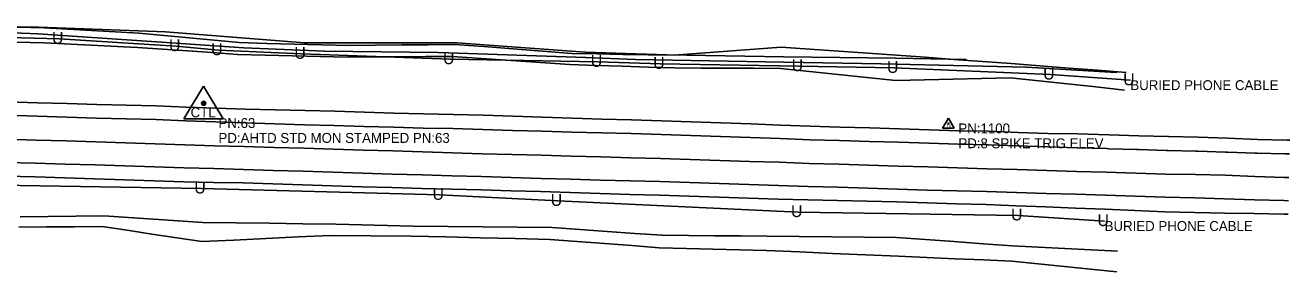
# Model space of a CAD drawing. Extents: x 976456 to 985170, y 1525951 to 1527080.
# Drawn here: x 983350 to 983988, y 1526256 to 1526381 of the extents above; entities that cross this region are included whole.
import ezdxf

# ---------------------------------------------------------------- set-up
doc = ezdxf.new("R2010")
doc.units = 0
for name, color, linetype in [('Default', 7, 'Continuous'), ('S_DITCHLINE', 7, 'Continuous'), ('S_EDGE_PAVEMENT', 7, 'Continuous'), ('S_FIBER_OPTIC_CABLE', 7, 'Continuous'), ('S_PAVEMENT_CROWN', 7, 'Continuous'), ('S_PRIMARY_CTL', 7, 'Continuous'), ('S_PRIMARY_CTL_ANNOT', 7, 'Continuous'), ('S_SECONDARY_CTL', 7, 'Continuous'), ('S_SECONDARY_CTL_ANNOT', 7, 'Continuous'), ('S_SHOULDER', 7, 'Continuous'), ('S_UNDERGROUND_CABLE', 7, 'Continuous'), ('S_UNDERGROUND_CABLE_ANNOT', 7, 'Continuous'), ('S_UTL_PT_SYM', 7, 'Continuous')]:
    doc.layers.add(name, color=color, linetype=linetype)

msp = doc.modelspace()

# ---------------------------------------------------------------- linework, layer by layer
at = {"layer": 'S_DITCHLINE'}
for points in [[(983905.63, 1526356.89), (983891.1, 1526358.02), (983876.57, 1526359.16), (983862.04, 1526360.29), (983847.51, 1526361.42), (983833.07, 1526362.47), (983818.62, 1526363.52), (983804.18, 1526364.56), (983789.74, 1526365.61), (983775.18, 1526366.63), (983760.61, 1526367.65), (983746.05, 1526368.67), (983731.48, 1526369.68), (983718, 1526368.66), (983704.52, 1526367.64), (983691.04, 1526366.62), (983677.56, 1526365.59), (983664.64, 1526365.83), (983651.73, 1526366.07), (983638.81, 1526366.31), (983625.89, 1526366.55), (983611.09, 1526367.68), (983596.29, 1526368.82), (983581.49, 1526369.96), (983566.69, 1526371.09), (983553.41, 1526370.95), (983540.12, 1526370.81), (983526.83, 1526370.67), (983513.54, 1526370.53), (983499.71, 1526370.89), (983485.87, 1526371.25), (983472.03, 1526371.61), (983458.19, 1526371.97), (983445.54, 1526373.18), (983432.9, 1526374.39), (983420.25, 1526375.6), (983407.6, 1526376.81), (983383.71, 1526378.12), (983359.82, 1526379.42), (983346.11, 1526379.83)], [(983904.73, 1526348.04), (983890.32, 1526349.6), (983875.92, 1526351.16), (983861.51, 1526352.72), (983847.1, 1526354.28), (983832.66, 1526353.91), (983818.23, 1526353.54), (983803.79, 1526353.17), (983789.36, 1526352.8), (983774.82, 1526354.33), (983760.28, 1526355.87), (983745.75, 1526357.41), (983731.21, 1526358.94), (983717.82, 1526359.01), (983704.43, 1526359.08), (983691.04, 1526359.15), (983677.65, 1526359.22), (983664.49, 1526359.64), (983651.32, 1526360.05), (983638.16, 1526360.47), (983625, 1526360.88), (983610.13, 1526361.9), (983595.26, 1526362.92), (983580.39, 1526363.94), (983565.53, 1526364.96), (983552.34, 1526364.9), (983539.16, 1526364.84), (983525.98, 1526364.78), (983512.8, 1526364.72), (983498.93, 1526365.05), (983485.07, 1526365.38), (983471.2, 1526365.72), (983457.33, 1526366.05), (983444.71, 1526366.94), (983432.1, 1526367.83), (983419.48, 1526368.72), (983406.86, 1526369.6), (983383.3, 1526370.76), (983359.74, 1526371.92), (983345.64, 1526372.19)], [(983901.19, 1526266.61), (983887.89, 1526267.32), (983874.59, 1526268.03), (983861.29, 1526268.74), (983847.99, 1526269.45), (983833.43, 1526270.47), (983818.88, 1526271.49), (983804.33, 1526272.52), (983789.77, 1526273.54), (983773.4, 1526273.74), (983757.03, 1526273.94), (983740.65, 1526274.14), (983724.28, 1526274.33), (983711.09, 1526274.42), (983697.9, 1526274.51), (983684.71, 1526274.6), (983671.52, 1526274.69), (983657.66, 1526275.68), (983643.79, 1526276.67), (983629.93, 1526277.66), (983616.06, 1526278.65), (983598.54, 1526278.82), (983581.02, 1526279.01), (983563.5, 1526279.19), (983545.98, 1526279.36), (983526.46, 1526279.86), (983506.93, 1526280.36), (983490.17, 1526280.56), (983473.41, 1526280.77), (983456.64, 1526280.98), (983439.88, 1526281.19), (983427.38, 1526282.01), (983414.88, 1526282.84), (983402.37, 1526283.66), (983389.87, 1526284.49), (983375.81, 1526284.32), (983361.76, 1526284.16), (983347.7, 1526284)], [(983900.88, 1526256.3), (983887.64, 1526257.65), (983874.39, 1526258.99), (983861.15, 1526260.33), (983847.91, 1526261.67), (983833.6, 1526262.28), (983819.3, 1526262.89), (983805, 1526263.51), (983790.7, 1526264.12), (983774.04, 1526264.84), (983757.37, 1526265.57), (983740.71, 1526266.29), (983724.05, 1526267.02), (983710.55, 1526267.36), (983697.05, 1526267.71), (983683.54, 1526268.05), (983670.04, 1526268.4), (983656.23, 1526269.47), (983642.42, 1526270.53), (983628.61, 1526271.59), (983614.8, 1526272.66), (983597.33, 1526273.08), (983579.86, 1526273.49), (983562.4, 1526273.91), (983544.93, 1526274.32), (983524.55, 1526274.49), (983504.18, 1526274.65), (983487.95, 1526273.86), (983471.73, 1526273.08), (983455.5, 1526272.3), (983439.27, 1526271.52), (983426.7, 1526273.42), (983414.13, 1526275.33), (983401.56, 1526277.24), (983388.99, 1526279.15), (983374.98, 1526279.06), (983360.97, 1526278.97), (983346.96, 1526278.88)]]:
    msp.add_lwpolyline(points, dxfattribs=at)
at = {"layer": 'S_EDGE_PAVEMENT'}
for points in [[(983341.18, 1526335.31), (983356.17, 1526334.78), (983371.16, 1526334.35), (983386.15, 1526333.89), (983401.15, 1526333.56), (983416.14, 1526333.1), (983431.12, 1526332.49), (983446.15, 1526332.01), (983461.14, 1526331.51), (983476.13, 1526331.01), (983491.12, 1526330.52), (983506.12, 1526330.16), (983521.11, 1526329.7), (983536, 1526329.22), (983550.99, 1526328.83), (983565.99, 1526328.57), (983580.98, 1526328.08), (983595.97, 1526327.69), (983610.96, 1526327.23), (983625.96, 1526326.83), (983640.95, 1526326.44), (983655.94, 1526326.04), (983670.93, 1526325.57), (983685.92, 1526325.02), (983700.91, 1526324.54), (983716, 1526324.05), (983730.99, 1526323.53), (983745.98, 1526322.95), (983745.98, 1526322.95), (983760.97, 1526322.5), (983775.96, 1526322.04), (983790.95, 1526321.68), (983805.94, 1526321.2), (983820.88, 1526320.72), (983835.88, 1526320.39), (983850.87, 1526319.92), (983865.86, 1526319.45), (983880.85, 1526318.91), (983895.84, 1526318.45), (983896.83, 1526318.42), (983910.83, 1526318.03), (983911.82, 1526318), (983925.7, 1526317.58), (983926.69, 1526317.55), (983940.69, 1526317.24), (983941.69, 1526317.22), (983955.68, 1526316.73), (983956.68, 1526316.7), (983970.68, 1526316.17), (983971.67, 1526316.13), (983985.67, 1526315.81), (983986.66, 1526315.79), (983987.92, 1526315.77)], [(983340.46, 1526311.52), (983355.45, 1526311.16), (983370.44, 1526310.66), (983385.44, 1526310.21), (983400.43, 1526309.74), (983415.42, 1526309.28), (983430.41, 1526308.85), (983445.37, 1526308.38), (983460.36, 1526307.91), (983475.35, 1526307.45), (983475.35, 1526307.45), (983490.35, 1526307), (983505.34, 1526306.51), (983520.33, 1526305.99), (983520.33, 1526305.99), (983535.39, 1526305.6), (983550.38, 1526305.21), (983565.38, 1526304.78), (983580.37, 1526304.32), (983580.37, 1526304.32), (983595.36, 1526303.92), (983610.35, 1526303.46), (983625.34, 1526303.08), (983640.33, 1526302.61), (983655.33, 1526302.19), (983655.33, 1526302.19), (983670.32, 1526301.79), (983685.31, 1526301.39), (983700.3, 1526300.89), (983715.22, 1526300.41), (983715.22, 1526300.41), (983730.2, 1526299.77), (983745.19, 1526299.26), (983760.19, 1526298.95), (983775.18, 1526298.47), (983790.17, 1526297.95), (983805.16, 1526297.45), (983820.2, 1526297.08), (983835.19, 1526296.74), (983850.18, 1526296.29), (983865.17, 1526295.86), (983880.17, 1526295.4), (983895.16, 1526294.89), (983910.15, 1526294.46), (983925.23, 1526293.98), (983940.23, 1526293.56), (983955.22, 1526293.14), (983955.22, 1526293.14), (983970.21, 1526292.66), (983970.21, 1526292.66), (983985.21, 1526292.21), (983985.21, 1526292.21), (983987.45, 1526292.17)]]:
    msp.add_lwpolyline(points, dxfattribs=at)
at = {"layer": 'S_FIBER_OPTIC_CABLE'}
for p, q in [((983357.07, 1526379.84), (983275.76, 1526380.75)), ((983420.95, 1526377.36), (983357.07, 1526379.84)), ((983356.57, 1526376.42), (983309.05, 1526378.18)), ((983419.01, 1526372.27), (983356.57, 1526376.42)), ((983491.02, 1526371.87), (983420.95, 1526377.36)), ((983460.54, 1526369.3), (983419.01, 1526372.27)), ((983501.17, 1526367.66), (983460.54, 1526369.3)), ((983491.14, 1526371.89), (983491.02, 1526371.87)), ((983567.99, 1526371.81), (983491.14, 1526371.89)), ((983558.49, 1526366.98), (983501.17, 1526367.66)), ((983632.95, 1526364.42), (983558.49, 1526366.98)), ((983632.74, 1526367.18), (983567.99, 1526371.81)), ((983673.79, 1526365.84), (983632.74, 1526367.18)), ((983658, 1526363.4), (983632.95, 1526364.42)), ((983732.98, 1526362.1), (983658, 1526363.4)), ((983732.84, 1526364.86), (983673.79, 1526365.84)), ((983789.3, 1526364.14), (983732.84, 1526364.86)), ((983781.94, 1526361.21), (983732.98, 1526362.1)), ((983855.1, 1526359.6), (983781.94, 1526361.21)), ((983824.69, 1526363.46), (983789.3, 1526364.14)), ((983900.54, 1526356.92), (983855.1, 1526359.6))]:
    msp.add_line(p, q, dxfattribs=at)
at = {"layer": 'S_PAVEMENT_CROWN'}
msp.add_lwpolyline([(983340.81, 1526323.18), (983355.8, 1526322.78), (983370.79, 1526322.38), (983385.79, 1526321.93), (983400.78, 1526321.47), (983415.77, 1526320.89), (983430.76, 1526320.42), (983445.75, 1526319.93), (983460.74, 1526319.46), (983475.74, 1526319.09), (983490.73, 1526318.67), (983505.72, 1526318.2), (983520.71, 1526317.77), (983535.69, 1526317.28), (983550.68, 1526316.89), (983565.67, 1526316.4), (983580.66, 1526315.84), (983595.66, 1526315.51), (983610.65, 1526315.11), (983625.64, 1526314.73), (983640.63, 1526314.34), (983655.62, 1526313.82), (983670.62, 1526313.43), (983685.61, 1526313.03), (983700.6, 1526312.48), (983715.6, 1526312.03), (983730.59, 1526311.56), (983745.58, 1526311), (983760.57, 1526310.57), (983775.56, 1526310.08), (983790.55, 1526309.58), (983805.55, 1526309.21), (983820.53, 1526308.75), (983835.52, 1526308.31), (983850.52, 1526307.91), (983865.51, 1526307.39), (983880.49, 1526306.96), (983895.48, 1526306.52), (983910.48, 1526306.08), (983925.46, 1526305.65), (983940.45, 1526305.37), (983955.45, 1526305.08), (983970.44, 1526304.45), (983985.43, 1526303.95), (983987.68, 1526303.9)], dxfattribs=at)
at = {"layer": 'S_PRIMARY_CTL'}
for p, q in [((983440.21, 1526350.07), (983430.17, 1526333.56)), ((983440.21, 1526350.07), (983450.03, 1526333.56)), ((983430.17, 1526333.56), (983450.03, 1526333.56))]:
    msp.add_line(p, q, dxfattribs=at)
for radius in [1.04, 0.609, 0.344]:
    msp.add_circle((983440.21, 1526341.37), radius, dxfattribs=at)
at = {"layer": 'S_SECONDARY_CTL'}
for p, q in [((983815.93, 1526333.78), (983812.92, 1526328.82)), ((983812.92, 1526328.82), (983818.88, 1526328.82)), ((983815.93, 1526333.78), (983818.88, 1526328.82))]:
    msp.add_line(p, q, dxfattribs=at)
for radius in [0.311, 0.183, 0.103]:
    msp.add_circle((983815.93, 1526331.17), radius, dxfattribs=at)
at = {"layer": 'S_SHOULDER'}
for points in [[(983341.38, 1526342.17), (983356.37, 1526341.65), (983371.36, 1526341.21), (983386.36, 1526340.77), (983401.35, 1526340.44), (983416.34, 1526340), (983431.33, 1526339.37), (983446.38, 1526338.91), (983461.37, 1526338.41), (983476.37, 1526338.13), (983491.36, 1526337.64), (983506.36, 1526337.38), (983521.35, 1526336.91), (983536.19, 1526336.43), (983551.18, 1526336.04), (983566.18, 1526335.77), (983581.17, 1526335.28), (983596.16, 1526334.89), (983611.15, 1526334.38), (983626.14, 1526333.88), (983641.13, 1526333.42), (983656.12, 1526333.02), (983671.11, 1526332.55), (983686.1, 1526331.93), (983701.09, 1526331.44), (983716.23, 1526330.96), (983731.21, 1526330.37), (983746.2, 1526329.79), (983761.19, 1526329.35), (983776.18, 1526328.89), (983791.18, 1526328.5), (983806.17, 1526328.01), (983821.08, 1526327.53), (983836.07, 1526327.2), (983851.06, 1526326.67), (983866.05, 1526326.09), (983881.05, 1526325.94), (983897.04, 1526325.44), (983912.03, 1526324.99), (983926.83, 1526324.56), (983941.82, 1526324.24), (983956.82, 1526323.77), (983971.81, 1526323.13), (983986.8, 1526322.79), (983988.05, 1526322.77)], [(983340.25, 1526304.51), (983355.24, 1526304.2), (983370.23, 1526303.64), (983385.22, 1526303.19), (983400.21, 1526302.7), (983415.21, 1526302.23), (983430.2, 1526301.74), (983445.14, 1526301.39), (983460.14, 1526301.12), (983475.13, 1526300.63), (983490.12, 1526300.11), (983505.11, 1526299.61), (983520.1, 1526299.2), (983535.22, 1526298.8), (983550.21, 1526298.38), (983565.2, 1526298), (983580.2, 1526297.62), (983595.19, 1526297.2), (983610.18, 1526296.74), (983625.17, 1526296.34), (983640.16, 1526295.88), (983655.15, 1526295.36), (983670.14, 1526294.93), (983685.14, 1526294.52), (983700.13, 1526294.01), (983714.99, 1526293.52), (983729.98, 1526292.94), (983744.98, 1526292.63), (983759.97, 1526292.27), (983774.97, 1526291.9), (983789.96, 1526291.52), (983804.95, 1526291.02), (983820.01, 1526290.65), (983835, 1526290.17), (983849.99, 1526289.6), (983864.98, 1526289.05), (983879.96, 1526288.44), (983894.95, 1526287.89), (983909.94, 1526287.27), (983925.09, 1526286.59), (983940.09, 1526286.21), (983955.08, 1526285.81), (983970.08, 1526285.78), (983985.08, 1526285.34), (983987.32, 1526285.3)]]:
    msp.add_lwpolyline(points, dxfattribs=at)
at = {"layer": 'S_UNDERGROUND_CABLE'}
for p, q in [((983367.37, 1526373.97), (983316.69, 1526375.31)), ((983426.37, 1526370.25), (983367.37, 1526373.97)), ((983447.64, 1526368.2), (983426.37, 1526370.25)), ((983489.59, 1526366.36), (983447.64, 1526368.2)), ((983564.59, 1526363.67), (983489.59, 1526366.36)), ((983639.11, 1526362.33), (983564.59, 1526363.67)), ((983670.62, 1526361.33), (983639.11, 1526362.33)), ((983740.46, 1526360.13), (983670.62, 1526361.33)), ((983788.55, 1526359.23), (983740.46, 1526360.13)), ((983867.31, 1526355.89), (983788.55, 1526359.23)), ((983907.68, 1526353.02), (983867.31, 1526355.89)), ((983439.12, 1526298.37), (983337.28, 1526299.97)), ((983559.3, 1526295.17), (983439.12, 1526298.37)), ((983618.91, 1526292.09), (983559.3, 1526295.17)), ((983740.11, 1526286.44), (983618.91, 1526292.09)), ((983851.11, 1526284.77), (983740.11, 1526286.44)), ((983894.71, 1526281.9), (983851.11, 1526284.77))]:
    msp.add_line(p, q, dxfattribs=at)
at = {"layer": 'S_UTL_PT_SYM'}
for points in [[(983357.07, 1526379.84), (983357.07, 1526379.89), (983357.07, 1526379.84), (983357.02, 1526379.84), (983357.07, 1526379.84), (983357.07, 1526379.79), (983357.07, 1526379.84), (983357.12, 1526379.84)], [(983356.57, 1526376.42), (983356.57, 1526376.47), (983356.57, 1526376.42), (983356.52, 1526376.42), (983356.57, 1526376.42), (983356.57, 1526376.37), (983356.57, 1526376.42), (983356.62, 1526376.42)], [(983420.95, 1526377.36), (983420.95, 1526377.41), (983420.95, 1526377.36), (983420.9, 1526377.36), (983420.95, 1526377.36), (983420.95, 1526377.31), (983420.95, 1526377.36), (983421, 1526377.36)], [(983419.01, 1526372.27), (983419.01, 1526372.32), (983419.01, 1526372.27), (983418.96, 1526372.27), (983419.01, 1526372.27), (983419.01, 1526372.22), (983419.01, 1526372.27), (983419.06, 1526372.27)], [(983460.54, 1526369.3), (983460.54, 1526369.35), (983460.54, 1526369.3), (983460.49, 1526369.3), (983460.54, 1526369.3), (983460.54, 1526369.25), (983460.54, 1526369.3), (983460.59, 1526369.3)], [(983491.02, 1526371.87), (983491.02, 1526371.92), (983491.02, 1526371.87), (983490.97, 1526371.87), (983491.02, 1526371.87), (983491.02, 1526371.82), (983491.02, 1526371.87), (983491.07, 1526371.87)], [(983491.14, 1526371.89), (983491.14, 1526371.94), (983491.14, 1526371.89), (983491.09, 1526371.89), (983491.14, 1526371.89), (983491.14, 1526371.84), (983491.14, 1526371.89), (983491.19, 1526371.89)], [(983501.17, 1526367.66), (983501.17, 1526367.71), (983501.17, 1526367.66), (983501.12, 1526367.66), (983501.17, 1526367.66), (983501.17, 1526367.61), (983501.17, 1526367.66), (983501.22, 1526367.66)], [(983558.49, 1526366.98), (983558.49, 1526367.03), (983558.49, 1526366.98), (983558.44, 1526366.98), (983558.49, 1526366.98), (983558.49, 1526366.93), (983558.49, 1526366.98), (983558.54, 1526366.98)], [(983567.99, 1526371.81), (983567.99, 1526371.86), (983567.99, 1526371.81), (983567.94, 1526371.81), (983567.99, 1526371.81), (983567.99, 1526371.76), (983567.99, 1526371.81), (983568.04, 1526371.81)], [(983632.74, 1526367.18), (983632.74, 1526367.23), (983632.74, 1526367.18), (983632.69, 1526367.18), (983632.74, 1526367.18), (983632.74, 1526367.13), (983632.74, 1526367.18), (983632.79, 1526367.18)], [(983632.95, 1526364.42), (983632.95, 1526364.47), (983632.95, 1526364.42), (983632.9, 1526364.42), (983632.95, 1526364.42), (983632.95, 1526364.37), (983632.95, 1526364.42), (983633, 1526364.42)], [(983658, 1526363.4), (983658, 1526363.45), (983658, 1526363.4), (983657.95, 1526363.4), (983658, 1526363.4), (983658, 1526363.35), (983658, 1526363.4), (983658.05, 1526363.4)], [(983673.79, 1526365.84), (983673.79, 1526365.89), (983673.79, 1526365.84), (983673.74, 1526365.84), (983673.79, 1526365.84), (983673.79, 1526365.79), (983673.79, 1526365.84), (983673.84, 1526365.84)], [(983732.84, 1526364.86), (983732.84, 1526364.91), (983732.84, 1526364.86), (983732.79, 1526364.86), (983732.84, 1526364.86), (983732.84, 1526364.81), (983732.84, 1526364.86), (983732.89, 1526364.86)], [(983732.98, 1526362.1), (983732.98, 1526362.15), (983732.98, 1526362.1), (983732.93, 1526362.1), (983732.98, 1526362.1), (983732.98, 1526362.05), (983732.98, 1526362.1), (983733.03, 1526362.1)], [(983781.94, 1526361.21), (983781.94, 1526361.26), (983781.94, 1526361.21), (983781.89, 1526361.21), (983781.94, 1526361.21), (983781.94, 1526361.16), (983781.94, 1526361.21), (983781.99, 1526361.21)], [(983789.3, 1526364.14), (983789.3, 1526364.19), (983789.3, 1526364.14), (983789.25, 1526364.14), (983789.3, 1526364.14), (983789.3, 1526364.09), (983789.3, 1526364.14), (983789.35, 1526364.14)], [(983824.69, 1526363.46), (983824.69, 1526363.51), (983824.69, 1526363.46), (983824.64, 1526363.46), (983824.69, 1526363.46), (983824.69, 1526363.41), (983824.69, 1526363.46), (983824.74, 1526363.46)], [(983855.1, 1526359.6), (983855.1, 1526359.65), (983855.1, 1526359.6), (983855.05, 1526359.6), (983855.1, 1526359.6), (983855.1, 1526359.55), (983855.1, 1526359.6), (983855.15, 1526359.6)], [(983900.54, 1526356.92), (983900.54, 1526356.97), (983900.54, 1526356.92), (983900.49, 1526356.92), (983900.54, 1526356.92), (983900.54, 1526356.87), (983900.54, 1526356.92), (983900.59, 1526356.92)]]:
    msp.add_lwpolyline(points, dxfattribs=at)

# ---------------------------------------------------------------- texts
at = {"layer": 'Default'}
for p in [(983363.74, 1526371.43), (983422.74, 1526367.71), (983444.01, 1526365.65), (983485.96, 1526363.82), (983560.96, 1526361.12), (983635.48, 1526359.78), (983666.99, 1526358.78), (983736.83, 1526357.58), (983784.92, 1526356.69), (983863.68, 1526353.35), (983904.05, 1526350.48), (983435.49, 1526295.82), (983555.67, 1526292.62), (983615.28, 1526289.54), (983736.48, 1526283.89), (983847.48, 1526282.22), (983891.08, 1526279.36)]:
    msp.add_text('U', height=6, rotation=360, dxfattribs=at).set_placement(p)
at = {"layer": 'S_PRIMARY_CTL'}
msp.add_text('CTL', height=5, rotation=360, dxfattribs=at).set_placement((983433.62, 1526334.29))
at = {"layer": 'S_PRIMARY_CTL_ANNOT'}
for s, p in [('PN:63', (983447.71, 1526328.87)), ('PD:AHTD STD MON STAMPED PN:63', (983447.71, 1526321.37))]:
    msp.add_text(s, height=5, dxfattribs=at).set_placement(p)
at = {"layer": 'S_SECONDARY_CTL'}
msp.add_text('TV', height=1.5, rotation=360, dxfattribs=at).set_placement((983814.73, 1526329.16))
at = {"layer": 'S_SECONDARY_CTL_ANNOT'}
for s, p in [('PN:1100', (983820.93, 1526326.17)), ('PD:8 SPIKE TRIG ELEV', (983820.93, 1526318.67))]:
    msp.add_text(s, height=5, dxfattribs=at).set_placement(p)
at = {"layer": 'S_UNDERGROUND_CABLE_ANNOT'}
for p in [(983907.68, 1526348.02), (983894.71, 1526276.9)]:
    msp.add_text('BURIED PHONE CABLE', height=5, dxfattribs=at).set_placement(p)

doc.saveas('drawing.dxf')
